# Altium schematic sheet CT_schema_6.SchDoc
size 218 x 258 mm
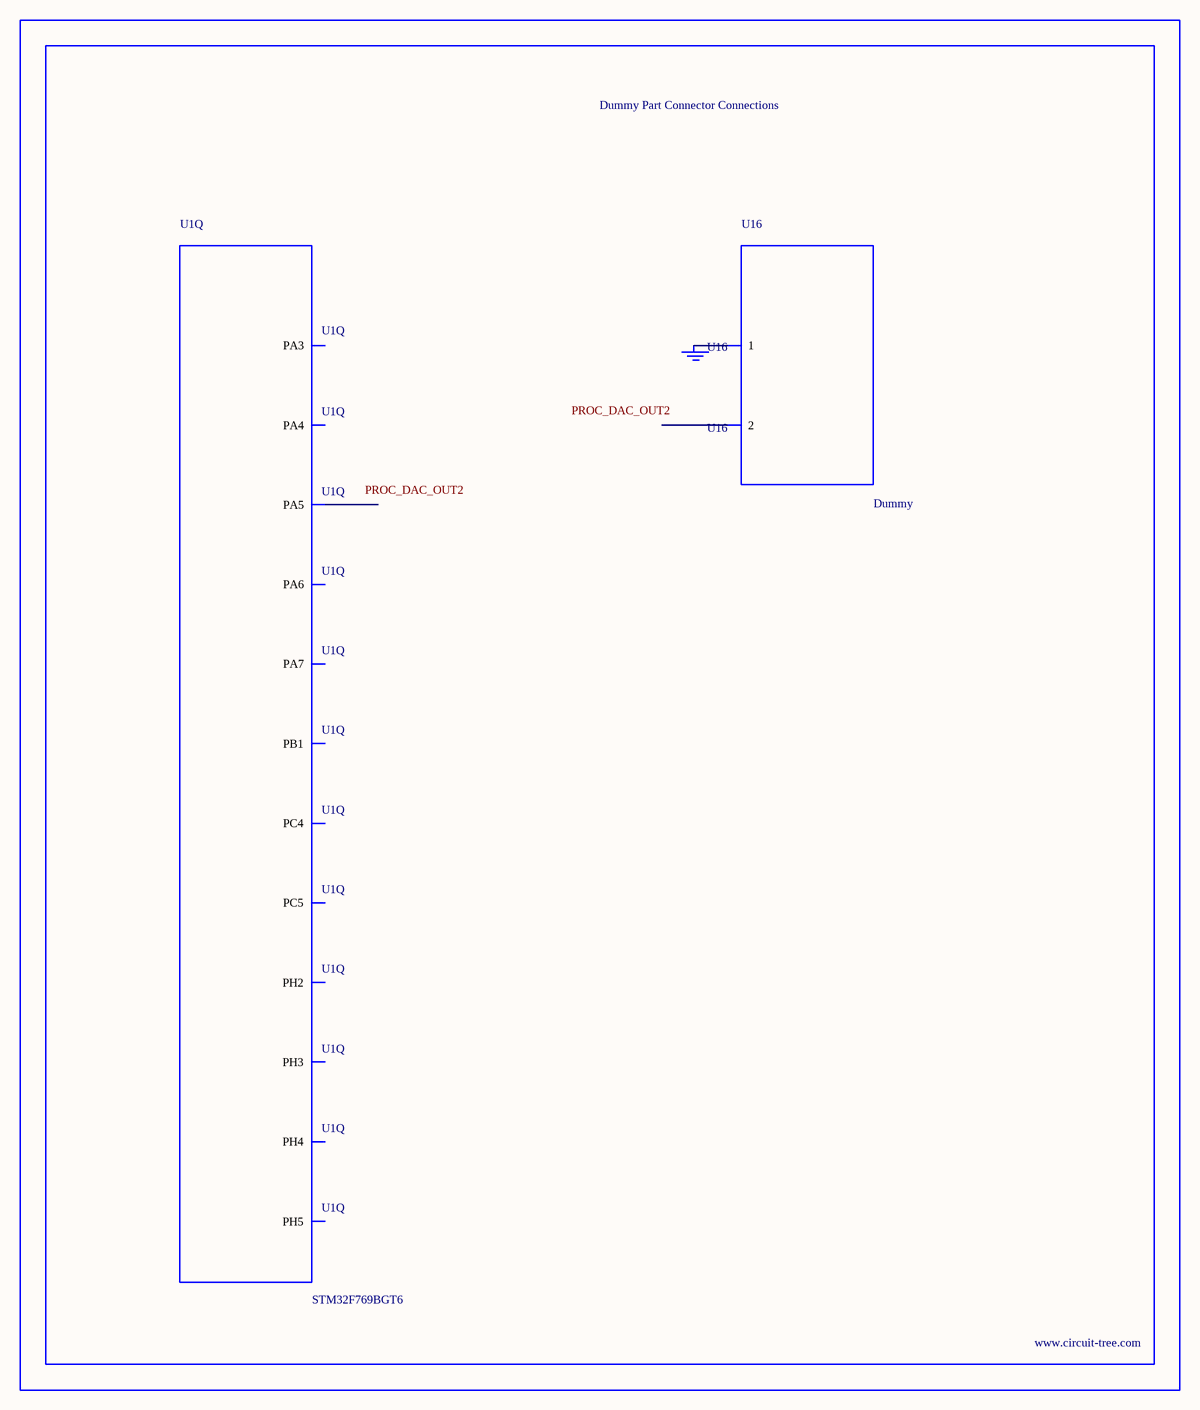
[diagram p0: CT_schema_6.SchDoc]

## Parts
BORDER5  (no value)
GND_INSTANCE_5_0  (no value)
U1  STM32F769BGT6  [LQFP208]  (part Q of 17)
U16  Dummy  [DUMMY_PACKAGE_198]

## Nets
NetGND_INSTANCE_5_0_0: GND_INSTANCE_5_0.0(GND) U16.1

Not connected (* = marked no-connect by the designer): U1 46(PH2) 47(PH3) 48(PH4) 49(PH5) 50(PA3) 53(PA4) 54(PA5) 55(PA6) 56(PA7) 57(PC4) 58(PC5) 62(PB1); U16 2

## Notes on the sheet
- Labels drawn without touching a wire or pin: PROC_DAC_OUT2

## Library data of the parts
BORDER5 = BORDER_PAGE5
GND_INSTANCE_5_0 = GND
